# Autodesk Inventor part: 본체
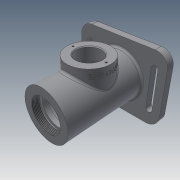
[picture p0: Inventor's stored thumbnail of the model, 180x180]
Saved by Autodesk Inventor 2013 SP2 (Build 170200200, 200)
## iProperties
Created: 2021-07
Part Number: 본체
Material: Generic
Document SubType Name: Modeling
Designer: kumcom17
Density: 1 g/cm^3
Author: kumcom17
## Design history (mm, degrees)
sketch "스케치1"
  geometry: L1 (-56, 0)-(59, 0); L2 (59, 0)-(59, 31); L3 (59, 31)-(-56, 31); L4 (-56, 31)-(-56, 0); L5 (-56, 21)-(-47, 21); L6 (-47, 21)-(-47, 24); L7 (-47, 24)-(-44, 24); L8 (-44, 24)-(-44, 20); L9 (-44, 20)-(-37.5, 20); L10 (-35, 17.5)-(-35, 17.5); L11 (-35, 17.5)-(-31.75, 17.5); L12 (-31.75, 17.5)-(-31.75, 18.5); L13 (-31.75, 18.5)-(-30, 18.5); L14 (-30, 18.5)-(-30, 17.5); L15 (-30, 17.5)-(-19, 17.5); L16 (-19, 17.5)-(-19, 23); L17 (-16, 26)-(16, 26); L18 (19, 23)-(19, 17.5); L19 (19, 17.5)-(30, 17.5); L20 (30, 17.5)-(30, 16); L21 (30, 16)-(32, 16); L22 (35, 13)-(35, 10); L23 (35, 10)-(37.7, 10); L24 (37.7, 10)-(37.7, 12.5); L25 (37.7, 12.5)-(44.3, 12.5); L26 (44.3, 12.5)-(45, 12.904); L27 (45, 12.904)-(45, 14.022); L28 (46.818, 16.779)-(59, 22); A1 r 3 centre (-16, 23) between (-16, 26) and (-19, 23); A2 r 3 centre (16, 23) between (19, 23) and (16, 26); A3 r 3 centre (32, 13) between (35, 13) and (32, 16); A4 r 3 centre (48, 14.022) between (46.818, 16.779) and (45, 14.022); A5 r 2.5 centre (-37.5, 17.5) between (-35, 17.5) and (-37.5, 20); 4 further points
  constraints: 56 end point, 13 parallel, 12 perpendicular, 10 point on circle, 10 tangent, 9 point on line, 5 centre point, 3 equal radius, 1 horizontal
  dimensions: "d0" = 115 distance of L3.end L2.end; "d1" = 31 distance of L2.end L1.end; "d2" = 56 distance from line of point (0, 0) L4; "d3" = 42 diameter of L5 L1; "d4" = 48 diameter of L7 L1; "d5" = 40 diameter of L9 L1; "d6" = 35 diameter of L11 L1; "d7" = 35 diameter of L15 L1; "d8" = 37 diameter of L13 L1; "d9" = 52 diameter of L17 L1; "d10" = 35 diameter of L19 L1; "d11" = 30 deg angle of L26 L25; "d12" = 32 diameter of point (45, 16) L1; "d13" = 25 diameter of L25 L1; "d14" = 44 diameter of L28.end L1; "d15" = 14 distance between parallel lines of L2 L27; "d16" = 0.7 horizontal distance of L25.end L26.end; "d17" = 7.3 distance between parallel lines of L24 L27; "d18" = 24 distance between parallel lines of L2 L22; "d19" = 20 diameter of L23 L1; "d20" = 32 diameter of L21 L1; "d21" = 21 distance between parallel lines of L10 L4; "d22" = 12 distance between parallel lines of L8 L4; "d23" = 3 distance between parallel lines of L8 L6; "d24" = 65 distance between parallel lines of L20 L10; "d25" = 11 distance of L18.end L19.end; "d26" = 38 distance of point (-19, 26) point (19, 26); "d27" = 11 distance of L14.end L15.end; "d28" = 1.75 distance of L12.end L13.end; "d29" = 3 radius of A1; "d30" = 2.5 radius of A5
revolve "회전1" sketch "스케치1" stored, may be unused: angle "d31" = 90 deg
chamfer "모따기1" distance "d32" = 1; stored, may be unused: second distance "d33" = 2, angle "d34" = 45 deg
sketch "스케치2"
  geometry: C1 r 31 at (0, 0) reference; C2 r 35 at (0, 0)
  constraints: 1 centre point, 1 coincident
  dimensions: "d35" = 70 diameter of C2
extrude "돌출1" join sketch "스케치2" distance "d36" = 3; taper "d37" = 0 deg
sketch "스케치3"
  geometry: L1 (-42, 45)-(42, 45); L2 (58, 29)-(58, -29); L3 (42, -45)-(-42, -45); L4 (-58, -29)-(-58, 29); L5 (-58, 45)-(58, -45); L6 (58, 45)-(-58, -45); C1 r 31 at (0, 0) reference; C2 r 35 at (0, 0) reference; A1 r 16 centre (-42, 29) between (-42, 45) and (-58, 29); A2 r 16 centre (-42, -29) between (-58, -29) and (-42, -45); A3 r 16 centre (42, -29) between (42, -45) and (58, -29); A4 r 16 centre (42, 29) between (58, 29) and (42, 45)
  constraints: 12 end point, 8 point on circle, 8 point on line, 8 tangent, 4 centre point, 3 equal radius, 2 midpoint, 2 parallel, 1 horizontal, 1 perpendicular
  dimensions: "d38" = 116 distance of L5.end L6.end; "d39" = 90 distance of L6.start L5.end; "d40" = 16 radius of A1
extrude "돌출2" join sketch "스케치3" distance "d41" = 10; taper "d42" = 0 deg
sketch "스케치4"
  geometry: L1 (40, 25)-(48, 25); L2 (48, 25)-(48, -25); L3 (48, -25)-(40, -25); L4 (40, -25)-(40, 25); L5 (40, 25)-(48, -25); L6 (48, 25)-(40, -25); C1 r 35 at (0, 0) reference; 4 further points
  constraints: 12 end point, 5 midpoint, 3 horizontal alignment, 2 parallel, 1 horizontal, 1 perpendicular, 4 other
  dimensions: "d43" = 8 distance of L2.end L3.end; "d44" = 50 distance of L1.end L2.end; "d45" = 44 distance of point (44, 0) C1.centre
extrude "돌출3" cut sketch "스케치4" stored distance "d46" = 10; taper "d47" = 0 deg
fillet "모깎기1" dims "d48" = 0.3
node "작업 평면1"
sketch "스케치5"
  geometry: C1 r 27 at (0, 0); 1 further point
  constraints: 1 centre point, 1 coincident
  dimensions: "d50" = 54 diameter of C1
extrude "돌출4" join sketch "스케치5" stored distance "d51" = 10; taper "d52" = 0 deg
sketch "스케치6"
  geometry: C1 r 27 at (0, 0) reference; C2 r 16 at (0, 0)
  constraints: 1 centre point, 1 coincident
  dimensions: "d53" = 32 diameter of C2
extrude "돌출5" cut sketch "스케치6" stored distance "d54" = 10; taper "d55" = 0 deg
chamfer "모따기2" distance "d56" = 1; stored, may be unused: second distance "d57" = 2, angle "d58" = 45 deg
fillet "모깎기2" dims "d59" = 3
sketch "스케치7"
  geometry: C1 r 27 at (0, 0) reference; 1 further point
  constraints: 1 vertical alignment
  dimensions: "d60" = 22 distance of C1.centre point (0, 22)
hole "구멍1" sketch "스케치7" at (0, 22) diameter "d61" = 2.459; stored, may be unused: countersink angle "d65" = 90 deg, drill point angle "d67" = 118 deg; dims "d62" = 6, "d63" = 4, "d64" = 2, "d66" = 8
node "작업 평면2"
sketch "스케치8"
  geometry: L1 (-27, 42)-(27, 42) reference; 2 further points
  constraints: 1 vertical alignment, 1 other
  dimensions: "d69" = 8 distance from line of point (0, 34) L1
feature "엠보싱1" sketch "스케치8" dims "d70" = 0.5, "d71" = 0
fillet "모깎기3" dims "d72" = 3
feature "스레드1" dims "d73" = 10, "d74" = 0
node "솔리드1"
mirror "대칭1"
mirror "대칭2"
other parameters: "d49" = 42
